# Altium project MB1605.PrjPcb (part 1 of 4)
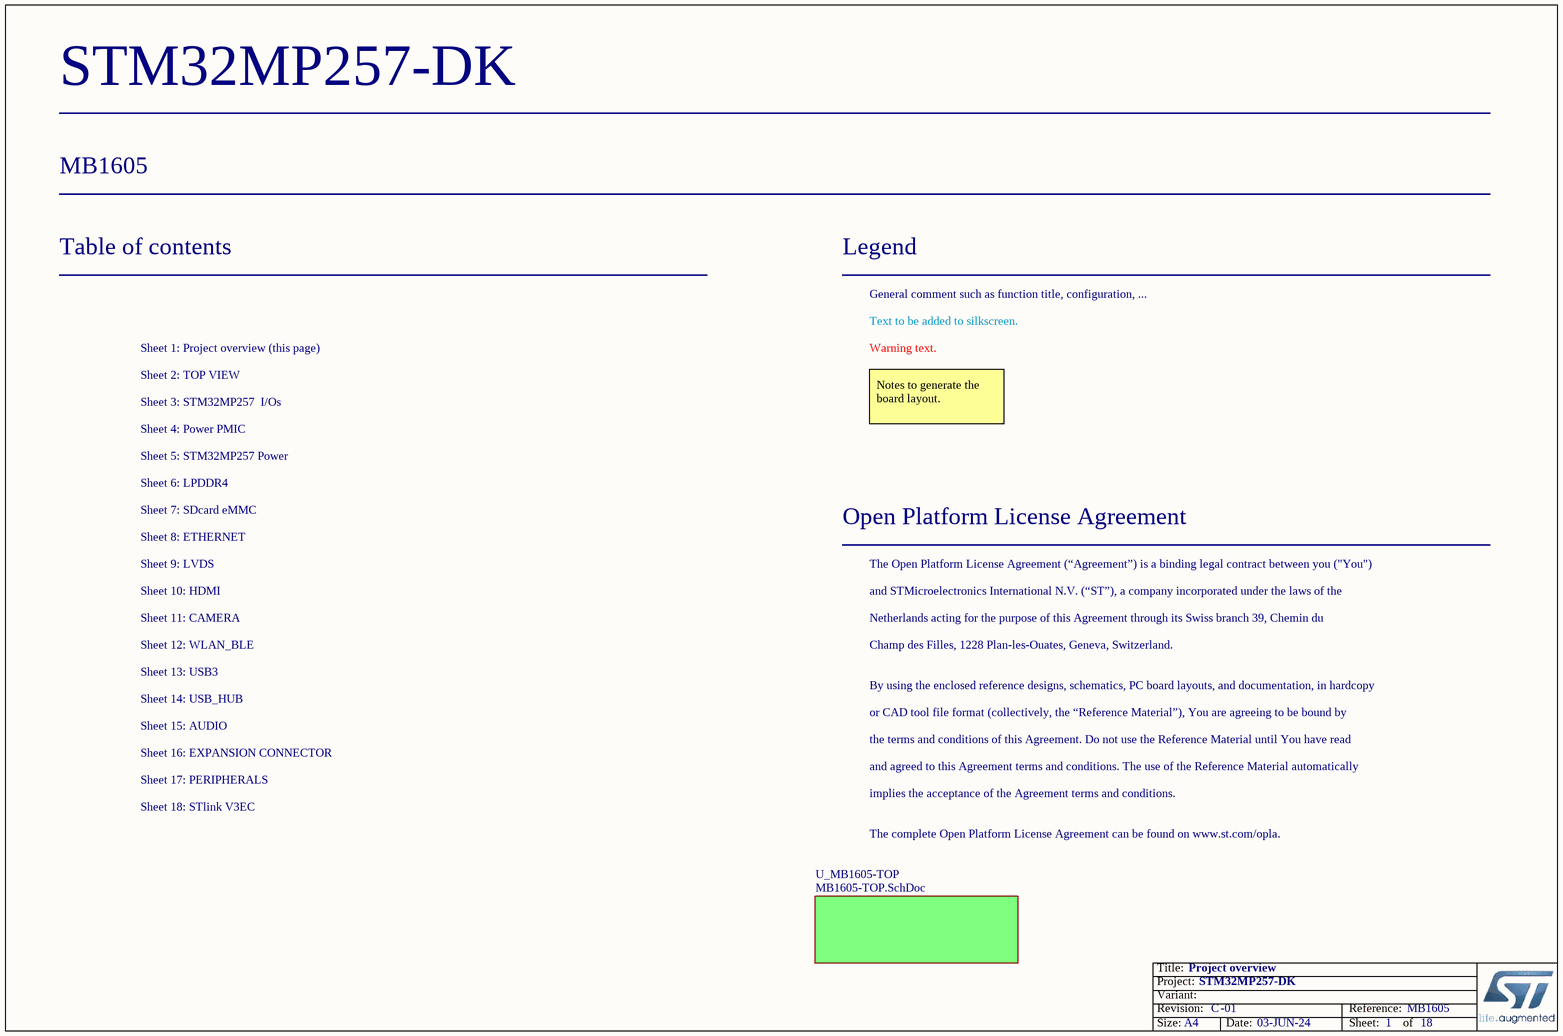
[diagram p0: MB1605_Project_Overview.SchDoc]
Board_Reference: MB1605; Board_PCB_Revision: C; Board_Name: STM32MP257-DK; Board_Document_Date: 03-JUN-24; Board_Assembly_Revision: 01
18 sheets, 641 parts. Net scope: flat (ports and power ports of the same name join across sheets).
Board file: MB1605.PcbDoc
Sheets:
  MB1605_Project_Overview.SchDoc
    U_MB1605-TOP = MB1605-TOP.SchDoc
      U_WLAN_BLUETOOTH = WLAN_BLUETOOTH.SchDoc
      U_Peripherals = Peripherals.SchDoc
      U_MP257_14x14 = MP257_14x14.SchDoc
      U_Power_PMIC = Power_PMIC.SchDoc
      U_Power_MPU = Power_MPU.SchDoc
      U_LVDS = LVDS.SchDoc
      U_STLINK_V3EC = STLINK_V3EC.SchDoc
      U_USB_HUB = USB_HUB.SchDoc
      U_USB3 = USB3.SchDoc
      U_CAMERA = CAMERA.SchDoc
      U_AUDIO = AUDIO.SchDoc
      U_Expansion_Connector = Expansion_Connector.SchDoc
      U_LPDDR4 = LPDDR4.SchDoc
      U_SDcard_eMMC = SDcard_eMMC.SchDoc
      U_ETHERNET = ETHERNET.SchDoc
      U_HDMI = HDMI.SchDoc

## Sheet MB1605_Project_Overview.SchDoc: Project overview
size A4; Date: Not used; ApprovedBy: Not used; CheckedBy: Not used; Author: Not used; CompanyName: STMicroelectronics; DrawnBy: Not used; Engineer: Not used; Organization: Not used; Address1: Not used; Address2: Not used; Address3: Not used; Address4: Not used; DocumentNumber: Not used; Revision: Not used; SheetNumber: 1; SheetTotal: 18

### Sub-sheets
U_MB1605-TOP = MB1605-TOP.SchDoc: no entries

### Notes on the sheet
- Table of contents
- Legend
- General comment such as function title, configuration, ...
- Sheet 1: Project overview (this page)
- Sheet 2: TOP VIEW
- Text to be added to silkscreen.
- Warning text.
- Sheet 3: STM32MP257  I/Os
- Sheet 4: Power PMIC
- Notes to generate the board layout.
- Sheet 5: STM32MP257 Power
- Sheet 7: SDcard eMMC
- Sheet 6: LPDDR4
- Sheet 8: ETHERNET
- Sheet 9: LVDS
- Open Platform License Agreement
- The Open Platform License Agreement (“Agreement”) is a binding legal contract between you ("You")
- Sheet 10: HDMI
- Sheet 11: CAMERA
- Sheet 12: WLAN_BLE
- and STMicroelectronics International N.V. (“ST”), a company incorporated under the laws of the
- Netherlands acting for the purpose of this Agreement through its Swiss branch 39, Chemin du
- Champ des Filles, 1228 Plan-les-Ouates, Geneva, Switzerland.
- Sheet 13: USB3
- Sheet 14: USB_HUB
- By using the enclosed reference designs, schematics, PC board layouts, and documentation, in hardcopy
- or CAD tool file format (collectively, the “Reference Material”), You are agreeing to be bound by
- Sheet 17: PERIPHERALS
- Sheet 16: EXPANSION CONNECTOR
- Sheet 15: AUDIO
- the terms and conditions of this Agreement. Do not use the Reference Material until You have read
- and agreed to this Agreement terms and conditions. The use of the Reference Material automatically
- Sheet 18: STlink V3EC
- implies the acceptance of the Agreement terms and conditions.
- The complete Open Platform License Agreement can be found on www.st.com/opla.

## Sheet MB1605-TOP.SchDoc: MB1605-TOP
size A3; Date: Not used; ApprovedBy: Not used; CheckedBy: Not used; Author: Not used; CompanyName: STMicroelectronics; DrawnBy: Not used; Engineer: Not used; Organization: Not used; Address1: Not used; Address2: Not used; Address3: Not used; Address4: Not used; DocumentNumber: Not used; Revision: Not used; SheetNumber: 2; SheetTotal: 18
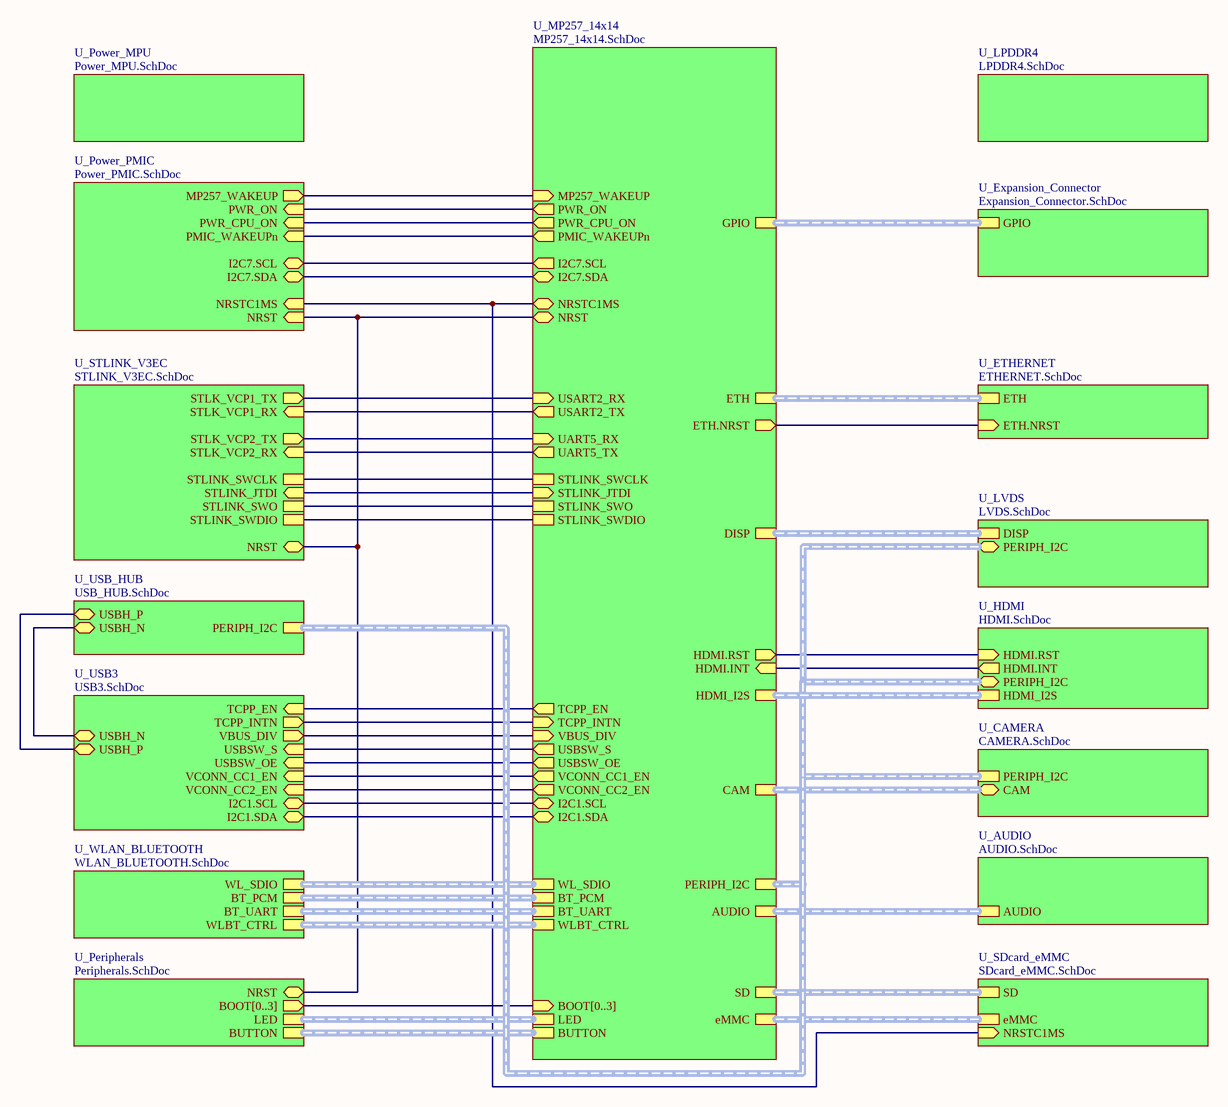
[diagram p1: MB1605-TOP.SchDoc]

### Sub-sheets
U_AUDIO = AUDIO.SchDoc: AUDIO (harness AUDIO)
U_CAMERA = CAMERA.SchDoc: CAM (bidir, harness CAMERA), PERIPH_I2C (harness PERIPH_I2C)
U_ETHERNET = ETHERNET.SchDoc: ETH.NRST (in), ETH (harness ETH1)
U_Expansion_Connector = Expansion_Connector.SchDoc: GPIO (harness GPIO)
U_HDMI = HDMI.SchDoc: HDMI.RST (in), HDMI.INT (out), PERIPH_I2C (bidir, harness PERIPH_I2C), HDMI_I2S (harness HDMI_I2S)
U_LPDDR4 = LPDDR4.SchDoc: no entries
U_LVDS = LVDS.SchDoc: DISP (harness DISP), PERIPH_I2C (bidir, harness PERIPH_I2C)
U_MP257_14x14 = MP257_14x14.SchDoc: NRST (bidir), PWR_ON (out), ETH (harness ETH1), BOOT[0..3] (in), LED (harness LED), BUTTON (harness BUTTON), UART5_TX (out), UART5_RX (in), STLINK_SWCLK, STLINK_JTDI (in), STLINK_SWO, STLINK_SWDIO, USART2_RX (in), NRSTC1MS (bidir), VBUS_DIV (in), TCPP_INTN (in), GPIO (harness GPIO), I2C7.SDA (bidir), I2C7.SCL (out), USART2_TX (out), DISP (harness DISP), PERIPH_I2C (harness PERIPH_I2C), ETH.NRST (out), I2C1.SCL (bidir), HDMI_I2S (harness HDMI_I2S), I2C1.SDA (bidir), PWR_CPU_ON (out), CAM (harness CAMERA), SD (harness SD), WL_SDIO (harness WL_SDIO), BT_PCM (harness BT_PCM), WLBT_CTRL (harness WL_BT_CTRL), BT_UART (harness BT_UART), AUDIO (harness AUDIO), MP257_WAKEUP (in), PMIC_WAKEUPn (out), HDMI.INT (in), HDMI.RST (out), USBSW_OE (out), USBSW_S (out), eMMC (harness eMMC), TCPP_EN (out), VCONN_CC1_EN (out), VCONN_CC2_EN (out)
U_Peripherals = Peripherals.SchDoc: NRST (bidir), BOOT[0..3] (out), LED (harness LED), BUTTON (harness BUTTON)
U_Power_MPU = Power_MPU.SchDoc: no entries
U_Power_PMIC = Power_PMIC.SchDoc: PMIC_WAKEUPn (in), NRST (in), I2C7.SCL (bidir), PWR_ON (in), PWR_CPU_ON (in), NRSTC1MS (in), I2C7.SDA (bidir), MP257_WAKEUP (out)
U_SDcard_eMMC = SDcard_eMMC.SchDoc: SD (harness SD), eMMC (harness eMMC), NRSTC1MS (in)
U_STLINK_V3EC = STLINK_V3EC.SchDoc: NRST (bidir), STLK_VCP2_TX (out), STLK_VCP2_RX (in), STLK_VCP1_TX (out), STLK_VCP1_RX (in), STLINK_SWO, STLINK_SWDIO, STLINK_SWCLK, STLINK_JTDI (in)
U_USB3 = USB3.SchDoc: TCPP_INTN (out), I2C1.SDA (bidir), I2C1.SCL (bidir), VBUS_DIV (out), USBH_P (bidir), USBH_N (bidir), USBSW_OE (in), USBSW_S (in), TCPP_EN (in), VCONN_CC1_EN (in), VCONN_CC2_EN (in)
U_USB_HUB = USB_HUB.SchDoc: USBH_P (bidir), USBH_N (bidir), PERIPH_I2C (harness PERIPH_I2C)
U_WLAN_BLUETOOTH = WLAN_BLUETOOTH.SchDoc: BT_PCM (harness BT_PCM), BT_UART (harness BT_UART), WL_SDIO (harness WL_SDIO), WLBT_CTRL (harness WL_BT_CTRL)

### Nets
(unnamed): sheet U_Peripherals/NRST, sheet U_MP257_14x14/NRST, sheet U_Power_PMIC/NRST, sheet U_STLINK_V3EC/NRST
(unnamed): sheet U_MP257_14x14/PWR_ON, sheet U_Power_PMIC/PWR_ON  [a separate net that carries the same name]
(unnamed): sheet U_MP257_14x14/UART5_TX, sheet U_STLINK_V3EC/STLK_VCP2_RX  [a separate net that carries the same name]
(unnamed): sheet U_MP257_14x14/UART5_RX, sheet U_STLINK_V3EC/STLK_VCP2_TX  [a separate net that carries the same name]
(unnamed): sheet U_MP257_14x14/STLINK_SWCLK, sheet U_STLINK_V3EC/STLINK_SWCLK  [a separate net that carries the same name]
(unnamed): sheet U_MP257_14x14/STLINK_JTDI, sheet U_STLINK_V3EC/STLINK_JTDI  [a separate net that carries the same name]
(unnamed): sheet U_MP257_14x14/STLINK_SWO, sheet U_STLINK_V3EC/STLINK_SWO  [a separate net that carries the same name]
(unnamed): sheet U_MP257_14x14/STLINK_SWDIO, sheet U_STLINK_V3EC/STLINK_SWDIO  [a separate net that carries the same name]
(unnamed): sheet U_MP257_14x14/USART2_RX, sheet U_STLINK_V3EC/STLK_VCP1_TX  [a separate net that carries the same name]
(unnamed): sheet U_MP257_14x14/NRSTC1MS, sheet U_Power_PMIC/NRSTC1MS, sheet U_SDcard_eMMC/NRSTC1MS  [a separate net that carries the same name]
(unnamed): sheet U_MP257_14x14/VBUS_DIV, sheet U_USB3/VBUS_DIV  [a separate net that carries the same name]
(unnamed): sheet U_MP257_14x14/TCPP_INTN, sheet U_USB3/TCPP_INTN  [a separate net that carries the same name]
(unnamed): sheet U_MP257_14x14/I2C7.SDA, sheet U_Power_PMIC/I2C7.SDA  [a separate net that carries the same name]
(unnamed): sheet U_MP257_14x14/I2C7.SCL, sheet U_Power_PMIC/I2C7.SCL  [a separate net that carries the same name]
(unnamed): sheet U_MP257_14x14/USART2_TX, sheet U_STLINK_V3EC/STLK_VCP1_RX  [a separate net that carries the same name]
(unnamed): sheet U_MP257_14x14/ETH.NRST, sheet U_ETHERNET/ETH.NRST  [a separate net that carries the same name]
(unnamed): sheet U_MP257_14x14/I2C1.SCL, sheet U_USB3/I2C1.SCL  [a separate net that carries the same name]
(unnamed): sheet U_MP257_14x14/I2C1.SDA, sheet U_USB3/I2C1.SDA  [a separate net that carries the same name]
(unnamed): sheet U_MP257_14x14/PWR_CPU_ON, sheet U_Power_PMIC/PWR_CPU_ON  [a separate net that carries the same name]
(unnamed): sheet U_MP257_14x14/MP257_WAKEUP, sheet U_Power_PMIC/MP257_WAKEUP  [a separate net that carries the same name]
(unnamed): sheet U_MP257_14x14/PMIC_WAKEUPn, sheet U_Power_PMIC/PMIC_WAKEUPn  [a separate net that carries the same name]
(unnamed): sheet U_MP257_14x14/HDMI.INT, sheet U_HDMI/HDMI.INT  [a separate net that carries the same name]
(unnamed): sheet U_MP257_14x14/HDMI.RST, sheet U_HDMI/HDMI.RST  [a separate net that carries the same name]
(unnamed): sheet U_MP257_14x14/USBSW_OE, sheet U_USB3/USBSW_OE  [a separate net that carries the same name]
(unnamed): sheet U_MP257_14x14/USBSW_S, sheet U_USB3/USBSW_S  [a separate net that carries the same name]
(unnamed): sheet U_MP257_14x14/TCPP_EN, sheet U_USB3/TCPP_EN  [a separate net that carries the same name]
(unnamed): sheet U_MP257_14x14/VCONN_CC1_EN, sheet U_USB3/VCONN_CC1_EN  [a separate net that carries the same name]
(unnamed): sheet U_MP257_14x14/VCONN_CC2_EN, sheet U_USB3/VCONN_CC2_EN  [a separate net that carries the same name]
(unnamed): sheet U_USB_HUB/USBH_P, sheet U_USB3/USBH_P  [a separate net that carries the same name]
(unnamed): sheet U_USB_HUB/USBH_N, sheet U_USB3/USBH_N  [a separate net that carries the same name]

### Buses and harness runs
bus sheet U_MP257_14x14/BOOT[0..3] = sheet U_Peripherals/BOOT[0..3]
harness sheet U_AUDIO/AUDIO = sheet U_MP257_14x14/AUDIO
harness sheet U_CAMERA/CAM = sheet U_MP257_14x14/CAM
harness sheet U_CAMERA/PERIPH_I2C = sheet U_HDMI/PERIPH_I2C = sheet U_LVDS/PERIPH_I2C = sheet U_MP257_14x14/PERIPH_I2C = sheet U_USB_HUB/PERIPH_I2C
harness sheet U_ETHERNET/ETH = sheet U_MP257_14x14/ETH
harness sheet U_Expansion_Connector/GPIO = sheet U_MP257_14x14/GPIO
harness sheet U_HDMI/HDMI_I2S = sheet U_MP257_14x14/HDMI_I2S
harness sheet U_LVDS/DISP = sheet U_MP257_14x14/DISP
harness sheet U_MP257_14x14/BT_PCM = sheet U_WLAN_BLUETOOTH/BT_PCM
harness sheet U_MP257_14x14/BT_UART = sheet U_WLAN_BLUETOOTH/BT_UART
harness sheet U_MP257_14x14/BUTTON = sheet U_Peripherals/BUTTON
harness sheet U_MP257_14x14/eMMC = sheet U_SDcard_eMMC/eMMC
harness sheet U_MP257_14x14/LED = sheet U_Peripherals/LED
harness sheet U_MP257_14x14/SD = sheet U_SDcard_eMMC/SD
harness sheet U_MP257_14x14/WL_SDIO = sheet U_WLAN_BLUETOOTH/WL_SDIO
harness sheet U_MP257_14x14/WLBT_CTRL = sheet U_WLAN_BLUETOOTH/WLBT_CTRL

## Sheet WLAN_BLUETOOTH.SchDoc: WLAN_BLUETOOTH
size A4; Date: 21-MAR-2018; Author: A.B; CompanyName: STMicroelectronics; Organization: MCD/TOOLS/GNB; Address1: 12, Rue Jules HOROWITZ; Address2: 38019 Grenoble; Address3: FRANCE; DocumentNumber: MB1605; Revision: B-01; SheetNumber: 12; SheetTotal: 18; Project: STM32MP257
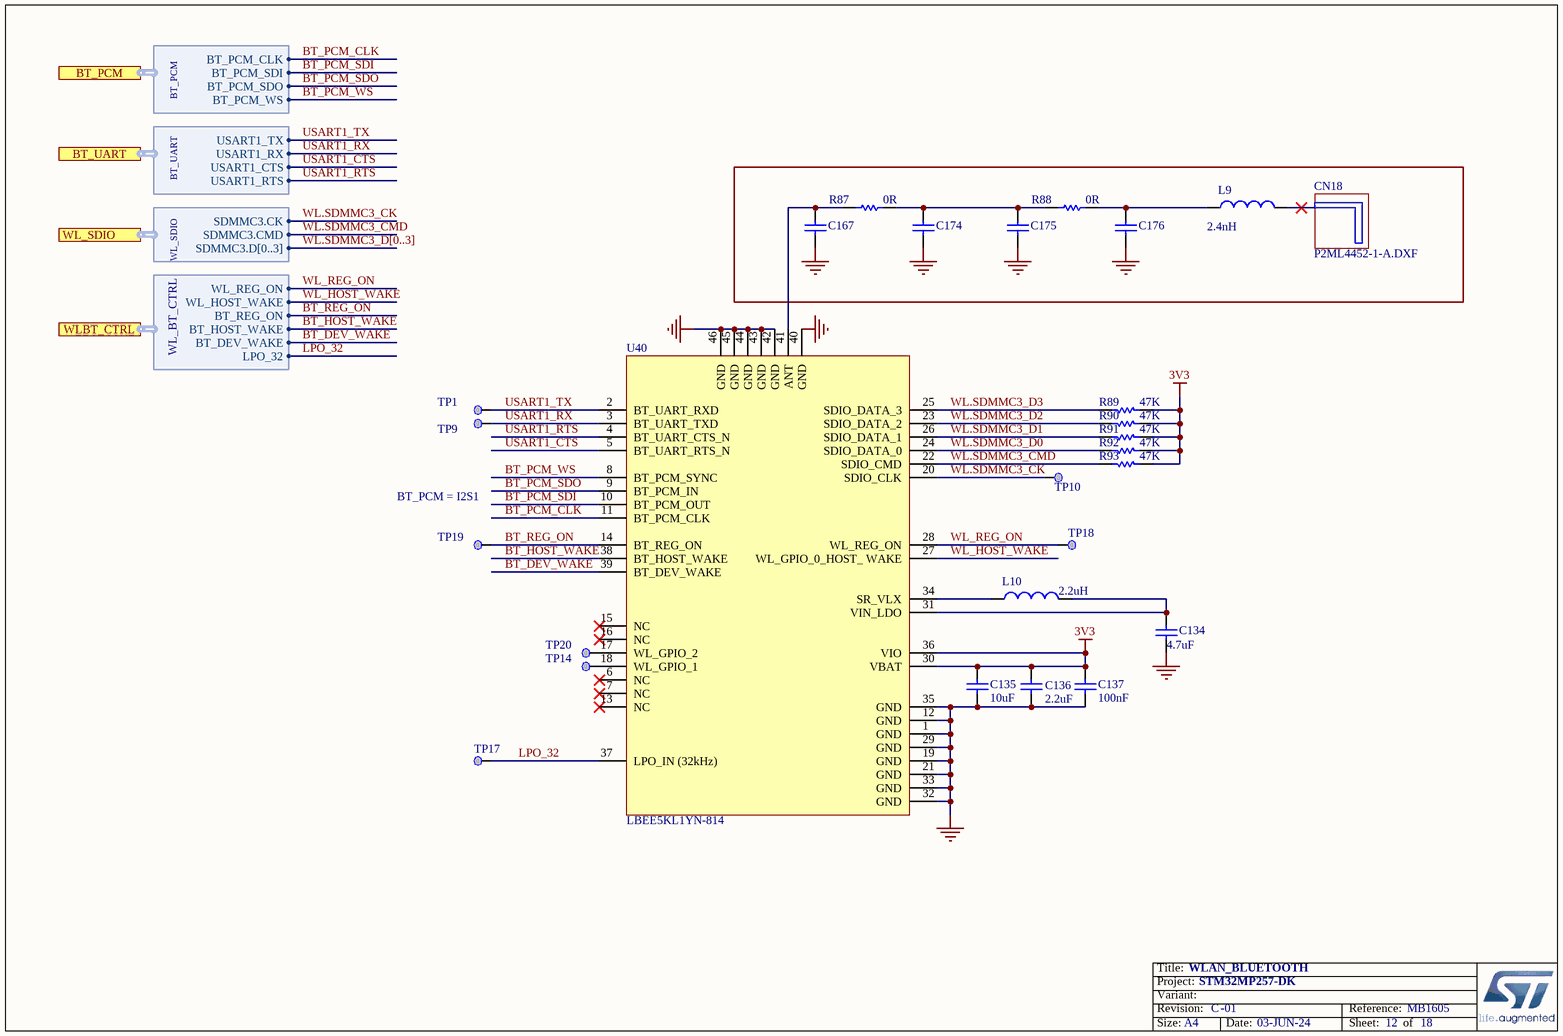
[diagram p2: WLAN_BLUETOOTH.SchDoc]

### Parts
C134  value 4.7uF  [C0402]  (hidden comment: Capacitor)
C135  value 10uF  [C0603]  (hidden comment: Capacitor)
C136  value 2.2uF  [C0603]  (hidden comment: Capacitor)
C137  value 100nF  [C0402]
C167  Capacitor  [C0402]  (value not drawn)
C174  Capacitor  [C0402]  (value not drawn)
C175  Capacitor  [C0402]  (value not drawn)
C176  Capacitor  [C0402]  (value not drawn)
CN18  value P2ML4452-1-A.DXF  [ANT_MURATA_TYPE-1-DX_P2ML4452-1-A_DXF]  (hidden comment: antenna_Wifi_BLE_Murata)  (no BOM)
L9  value 2.4nH  [IND_0402_MURATA_LQW15AN2N4C00X]  (hidden comment: Inductor)
L10  value 2.2uH  [L0603]  (hidden comment: Inductor)
R87  value 0R  [R0402]  (hidden comment: Resistor)
R88  value 0R  [R0402]  (hidden comment: Resistor)
R89  value 47K  [R0402]  (hidden comment: Resistor)
R90  value 47K  [R0402]  (hidden comment: Resistor)
R91  value 47K  [R0402]  (hidden comment: Resistor)
R92  value 47K  [R0402]  (hidden comment: Resistor)
R93  value 47K  [R0402]  (hidden comment: Resistor)
TP1  Test Point  [TP_SMD_0-6MM]  (value not drawn)  (no BOM)
TP9  Test Point  [TP_SMD_0-6MM]  (value not drawn)  (no BOM)
TP10  Test Point  [TP_SMD_0-6MM]  (value not drawn)  (no BOM)
TP14  Test Point  [TP_SMD_0-6MM]  (value not drawn)  (no BOM)
TP17  Test Point  [TP_SMD_0-6MM]  (value not drawn)  (no BOM)
TP18  Test Point  [TP_SMD_0-6MM]  (value not drawn)  (no BOM)
TP19  Test Point  [TP_SMD_0-6MM]  (value not drawn)  (no BOM)
TP20  Test Point  [TP_SMD_0-6MM]  (value not drawn)  (no BOM)
U40  LBEE5KL1YN-814  [MOD_WLAN-BT_MURATA_LBEE5KL1YN-814]

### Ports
BT_PCM (harness BT_PCM), BT_UART (harness BT_UART), WL_SDIO (harness WL_SDIO), WLBT_CTRL (harness WL_BT_CTRL)

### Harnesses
BT_PCM: BT_PCM_CLK, BT_PCM_SDI, BT_PCM_SDO, BT_PCM_WS
BT_UART: USART1_TX, USART1_RX, USART1_CTS, USART1_RTS
WL_SDIO: SDMMC3.CMD, SDMMC3.CK, SDMMC3.D[0..3]
WL_BT_CTRL: WL_REG_ON, WL_HOST_WAKE, BT_REG_ON, BT_HOST_WAKE, BT_DEV_WAKE, LPO_32

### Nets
3V3: C135.2 C136.2 C137.2 R89.1 R90.1 R91.1 R92.1 R93.1 U40.30(VBAT) U40.36(VIO)
GND: C134.1 C135.1 C136.1 C137.1 C167.1 C174.1 C175.1 C176.1 U40.1(GND) U40.12(GND) U40.19(GND) U40.21(GND) U40.29(GND) U40.32(GND) U40.33(GND) U40.35(GND) U40.40(GND) U40.42(GND) U40.43(GND) U40.44(GND) U40.45(GND) U40.46(GND)
BT_DEV_WAKE: U40.39(BT_DEV_WAKE) ; port WLBT_CTRL.BT_DEV_WAKE
BT_HOST_WAKE: U40.38(BT_HOST_WAKE) ; port WLBT_CTRL.BT_HOST_WAKE
BT_PCM_CLK: U40.11(BT_PCM_CLK) ; port BT_PCM.BT_PCM_CLK
BT_PCM_SDI: U40.10(BT_PCM_OUT) ; port BT_PCM.BT_PCM_SDI
BT_PCM_SDO: U40.9(BT_PCM_IN) ; port BT_PCM.BT_PCM_SDO
BT_PCM_WS: U40.8(BT_PCM_SYNC) ; port BT_PCM.BT_PCM_WS
BT_REG_ON: TP19.1 U40.14(BT_REG_ON) ; port WLBT_CTRL.BT_REG_ON
LPO_32: TP17.1 U40.37(LPO_IN_(32kHz)) ; port WLBT_CTRL.LPO_32
USART1_CTS: U40.5(BT_UART_RTS_N) ; port BT_UART.USART1_CTS
USART1_RTS: U40.4(BT_UART_CTS_N) ; port BT_UART.USART1_RTS
USART1_RX: TP9.1 U40.3(BT_UART_TXD) ; port BT_UART.USART1_RX
USART1_TX: TP1.1 U40.2(BT_UART_RXD) ; port BT_UART.USART1_TX
WL.SDMMC3_CK: TP10.1 U40.20(SDIO_CLK) ; port WL_SDIO.SDMMC3.CK
WL.SDMMC3_CMD: R93.2 U40.22(SDIO_CMD) ; port WL_SDIO.SDMMC3.CMD
WL.SDMMC3_D0: R92.2 U40.24(SDIO_DATA_0)
WL.SDMMC3_D1: R91.2 U40.26(SDIO_DATA_1)
WL.SDMMC3_D2: R90.2 U40.23(SDIO_DATA_2)
WL.SDMMC3_D3: R89.2 U40.25(SDIO_DATA_3)
WL_HOST_WAKE: U40.27(WL_GPIO_0_HOST__WAKE) ; port WLBT_CTRL.WL_HOST_WAKE
WL_REG_ON: TP18.1 U40.28(WL_REG_ON) ; port WLBT_CTRL.WL_REG_ON
NetC134_2: C134.2 L10.2 U40.31(VIN_LDO)
NetC167_2: C167.2 R87.2 U40.41(ANT)
NetC174_2: C174.2 C175.2 R87.1 R88.2
NetC176_2: C176.2 L9.1 R88.1
NetL10_1: L10.1 U40.34(SR_VLX)
NetTP14_1: TP14.1 U40.18(WL_GPIO_1)
NetTP20_1: TP20.1 U40.17(WL_GPIO_2)

Not connected (* = marked no-connect by the designer): L9 2*; U40 6(NC)* 7(NC)* 13(NC)* 15(NC)* 16(NC)*

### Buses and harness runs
bus WL.SDMMC3_D[0..3]

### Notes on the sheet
- (near TP19) BT_PCM = I2S1

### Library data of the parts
C134 = MCD-01356: Capacitor, MLCC, 4.7uF, 6V3, X5R, 20%, 0402, T=0,5mm; Manufacturer_Part_Number: GRM155R60J475ME47; Manufacturer: MURATA; Alternate_Manufacturer_Part_Number: GRM155R60J475ME87; Part_Preference: Recommended; Provided_By: SUBCO; Order_Code_RS: 814-5230; ECCN_EU: NEC; ECCN_US: EAR99; Component_Country_Of_Origin: Japan; ID: 3456; ShowFields: YES
C135 = MCD-00099: Capacitor, MLCC, 10uF, 10V, X5R, 10%, 0603, T=0,8mm; Manufacturer_Part_Number: GRM188R61A106KE69D; Manufacturer: MURATA; Part_Preference: Recommended; ECCN_US: EAR99; ECCN_EU: NEC; Provided_By: SUBCO; Initial_Board_Reference: MB1262; Order_Code_RS: 170-6168; Component_Country_Of_Origin: Japan; ID: 2770; ShowFields: YES
C136 = MCD-00012: Capacitor, MLCC, 2.2uF, 10V, X5R, 10%, 0603, T=0,8mm; Manufacturer_Part_Number: CC0603KRX5R6BB225; Manufacturer: YAGEO; Alternate_Manufacturer_Part_Number: C0603C225K8PACTU; Alternate_Manufacturer: KEMET; BMS_Part_Number: 9142010; Part_Preference: Recommended; ECCN_US: EAR99; ECCN_EU: NEC; Provided_By: SUBCO; Initial_Board_Reference: MB1274; Component_Country_Of_Origin: China; ID: 2467; ShowFields: YES
C137 = MCD-00006: Capacitor,100nF,16V,X7R,10%,0402; Manufacturer_Part_Number: CC0402KRX7R7BB104; Manufacturer: YAGEO; Alternate_Manufacturer: MURATA; Alternate_Manufacturer_Part_Number: GCM155R71C104KA55D; Part_Preference: Recommended; Partial_Alternate_Internal_Part_Number: MCD-03299; ECCN_US: EAR99; ECCN_EU: NEC; Provided_By: SUBCO; Initial_Board_Reference: MB1274; Order_Code_RS: 616-9701; Component_Country_Of_Origin: China; ID: 2474; ShowFields: YES; Alternate_EMS: M
C167 C174-C176 = MCD-00200: Capacitor, MLCC, 12pF, 50V, NPO, 5%, 0402, T=0,5mm; Manufacturer_Part_Number: CC0402JRNPO9BN120; Manufacturer: YAGEO; Part_Preference: Recommended; Provided_By: SUBCO; ECCN_EU: NEC; ECCN_US: EAR99; Component_Country_Of_Origin: China; ID: 2667; ShowFields: YES
CN18 = MCD-00656: Murata_Type1DX_AntennaDesign_P2ML4452-1-A.DXF; Part_Type: Misc; Manufacturer: MURATA; Part_Preference: Recommended; Initial_Board_Reference: MB1272; Component_Country_Of_Origin: Unknown; ID: 3086; ShowFields: YES
L9 = MCD-00657: Inductor,2.4nH,+-0.2nH,0.05R,0.85A,0402; Manufacturer_Part_Number: LQW15AN2N4C00#; Manufacturer: MURATA; Part_Preference: Recommended; Provided_By: SUBCO; Initial_Board_Reference: MB1272; Order_Code_RS: 177-6240; Component_Country_Of_Origin: Japan; ID: 3088; ShowFields: YES
L10 = MCD-00659: Inductor, 2.2µH, 20%, Isat 0.35A, DCR 0.2Ohm, 0603; Manufacturer_Part_Number: LQM18PN2R2MGH; Manufacturer: MURATA; Part_Preference: Recommended; Provided_By: SUBCO; Initial_Board_Reference: MB1272; Component_Country_Of_Origin: Japan; ID: 3085; ShowFields: YES
R87 R88 = MCD-00052: Resistor,0R,0402,5%,1/16W; Manufacturer_Part_Number: RC0402JR-070RL; Manufacturer: YAGEO; Part_Preference: Recommended; ECCN_US: EAR99; ECCN_EU: NEC; Provided_By: SUBCO; Initial_Board_Reference: MB1274; Order_Code_RS: 618-5804; Component_Country_Of_Origin: China; ID: 2540; ShowFields: YES
R89-R93 = MCD-00063: Resistor,47K,0402,1%,1/16W; Manufacturer_Part_Number: RC0402FR-0747KL; Manufacturer: YAGEO; Part_Preference: Recommended; ECCN_US: EAR99; ECCN_EU: NEC; Provided_By: SUBCO; Initial_Board_Reference: MB1274; Component_Country_Of_Origin: China; ID: 2528; ShowFields: YES
TP1 TP9 TP10 TP14 TP17-TP20 = MCD-00631: Test Point 0.6mm; Part_Type: Misc; Part_Preference: Recommended; Initial_Board_Reference: MB1264; ID: 3108; ShowFields: YES
U40 = MCD-03465: IC, IEEE802.11b/g/n W-LAN + Bluetooth 5.2(BR/EDR/BLE) module; Part_Preference: Recommended; Manufacturer: MURATA; Component_Country_Of_Origin: China°; ShowFields: YES; ID: 5581

## Sheet Peripherals.SchDoc: Peripherals
size A4; Date: 01-DEC-2013; CompanyName: STMicroelectronics; Organization: Microcontrollers Division; Address1: 12, Rue Jules HOROWITZ; Address2: 38019 Grenoble; Address3: FRANCE; DocumentNumber: MB1272; Revision: A-01; SheetNumber: 17; SheetTotal: 18; Project: STM32MP15-DISCO PI
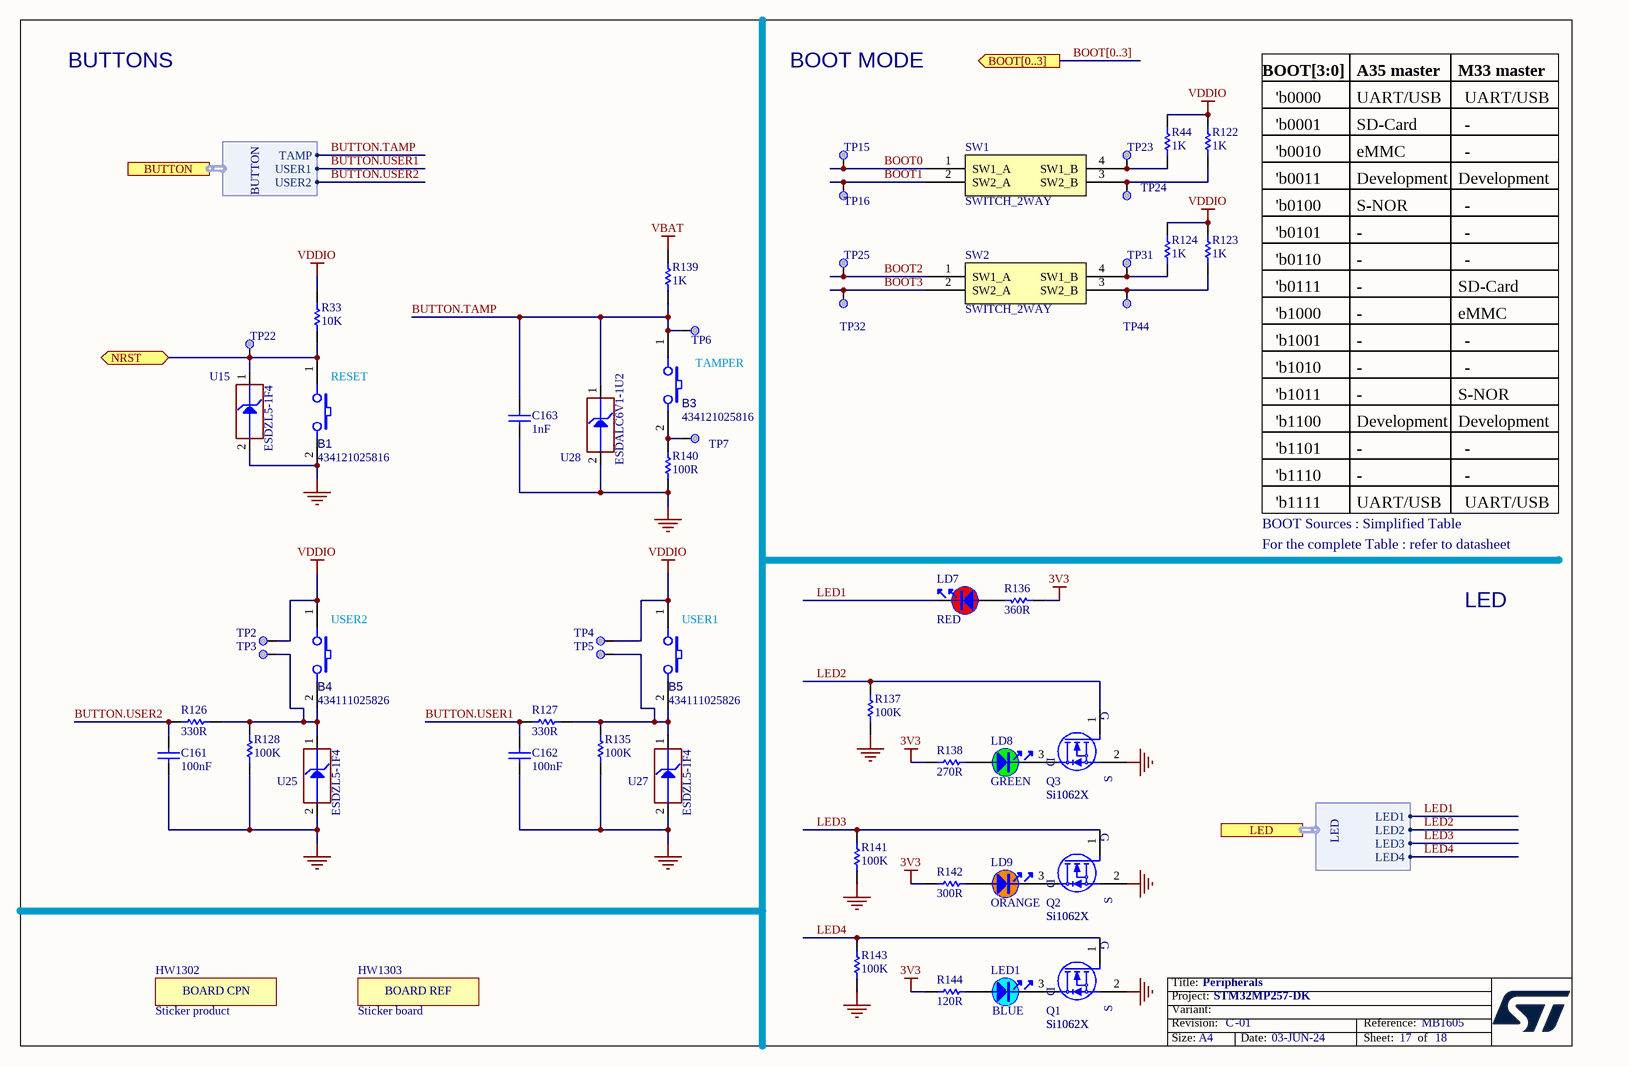
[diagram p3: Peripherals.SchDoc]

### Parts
B1  value 434121025816  [SWI_WE_434121025816]  (hidden comment: SW_PUSH_SMD_2P)
B3  value 434121025816  [SWI_WE_434121025816]  (hidden comment: SW_PUSH_SMD_2P)
B4  value 434111025826  [SWI_WE_4341x10258x6]  (hidden comment: SW_PUSH_SMD_2P)
B5  value 434111025826  [SWI_WE_4341x10258x6]  (hidden comment: SW_PUSH_SMD_2P)
C161  value 100nF  [C0402]  (hidden comment: Capacitor)
C162  value 100nF  [C0402]  (hidden comment: Capacitor)
C163  value 1nF  [C0402]  (hidden comment: Capacitor)
HW1302  value Sticker product  [STICKER_BOARD-CPN_25X5]  (hidden comment: ​PCH W35 footprint requested to have a space on board for stickers.)  (mechanical)
HW1303  value Sticker board  [STICKER_BOARD-REF_25X5]  (hidden comment: STICKER_BOARD_REF)  (mechanical)
LD7  value RED  [LED_0603_VISHAY_VLMS1300-GS08_RED_1A2K_H0P8]  (hidden comment: LED_red)
LD8  value GREEN  [LED_0603_OSRAM_LG-Q396-PS-35_GREEN_1A2K_H0P4]  (hidden comment: LED_green)
LD9  value ORANGE  [LED_0603_OSRAM_LO-Q976-PS-25_ORANGE_1A2K_H0P8]  (hidden comment: LED_orange)
LED1  value BLUE  [LED_0603_OSRAM_LB-Q39G-L2OO-35-1_BLUE_1A2K_H0P4]
Q1  value Si1062X  Manufacturer_Part_Number: Si1062X  [MOS_SC89-3L]  (hidden comment: MOSFET_N-CHANNEL)
Q2  value Si1062X  Manufacturer_Part_Number: Si1062X  [MOS_SC89-3L]  (hidden comment: MOSFET_N-CHANNEL)
Q3  value Si1062X  Manufacturer_Part_Number: Si1062X  [MOS_SC89-3L]  (hidden comment: MOSFET_N-CHANNEL)
R33  value 10K  [R0402]  (hidden comment: Resistor)
R44  value 1K  [R0402]  (hidden comment: Resistor)
R122  value 1K  [R0402]  (hidden comment: Resistor)
R123  value 1K  [R0402]  (hidden comment: Resistor)
R124  value 1K  [R0402]  (hidden comment: Resistor)
R126  value 330R  [R0402]  (hidden comment: Resistor)
R127  value 330R  [R0402]  (hidden comment: Resistor)
R128  value 100K  [R0402]  (hidden comment: Resistor)
R135  value 100K  [R0402]  (hidden comment: Resistor)
R136  value 360R  [R0402]  (hidden comment: Resistor)
R137  value 100K  [R0402]  (hidden comment: Resistor)
R138  value 270R  [R0402]  (hidden comment: Resistor)
R139  value 1K  [R0402]  (hidden comment: Resistor)
R140  value 100R  [R0402]  (hidden comment: Resistor)
R141  value 100K  [R0402]  (hidden comment: Resistor)
R142  value 300R  [R0402]  (hidden comment: Resistor)
R143  value 100K  [R0402]  (hidden comment: Resistor)
R144  value 120R  [R0402]
SW1  SWITCH_2WAY  [SWI_C&K_SDA02H1SBD_2POS]
SW2  SWITCH_2WAY  [SWI_C&K_SDA02H1SBD_2POS]
TP2  Test Point  [TP_SMD_1MM]  (value not drawn)  (no BOM)
TP3  Test Point  [TP_SMD_1MM]  (value not drawn)  (no BOM)
TP4  Test Point  [TP_SMD_1MM]  (value not drawn)  (no BOM)
TP5  Test Point  [TP_SMD_1MM]  (value not drawn)  (no BOM)
TP6  Test Point  [TP_SMD_1MM]  (value not drawn)  (no BOM)
TP7  Test Point  [TP_SMD_1MM]  (value not drawn)  (no BOM)
TP15  Test Point  [TP_SMD_1MM]  (value not drawn)  (no BOM)
TP16  Test Point  [TP_SMD_1MM]  (value not drawn)  (no BOM)
TP22  Test Point  [TP_SMD_1MM]  (value not drawn)  (no BOM)
TP23  Test Point  [TP_SMD_1MM]  (value not drawn)  (no BOM)
TP24  Test Point  [TP_SMD_1MM]  (value not drawn)  (no BOM)
TP25  Test Point  [TP_SMD_1MM]  (value not drawn)  (no BOM)
TP31  Test Point  [TP_SMD_1MM]  (value not drawn)  (no BOM)
TP32  Test Point  [TP_SMD_1MM]  (value not drawn)  (no BOM)
TP44  Test Point  [TP_SMD_1MM]  (value not drawn)  (no BOM)
U15  value ESDZL5-1F4  [ESD_ST0201]  (hidden comment: ESD-TRANSIL)
U25  value ESDZL5-1F4  [ESD_ST0201]  (hidden comment: ESD-TRANSIL)
U27  value ESDZL5-1F4  [ESD_ST0201]  (hidden comment: ESD-TRANSIL)
U28  value ESDALC6V1-1U2  [ESD_ST0201]  (hidden comment: ESD-TRANSIL)

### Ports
BOOT[0..3] (out), BUTTON (harness BUTTON), LED (harness LED), NRST (bidir)

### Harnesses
BUTTON: TAMP, USER1, USER2
LED: LED1, LED2, LED3, LED4

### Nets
3V3: R136.1 R138.2 R142.2 R144.1
GND: B1.2 C161.1 C162.1 C163.1 Q1.2(S) Q2.2(S) Q3.2(S) R128.1 R135.1 R137.1 R140.2 R141.1 R143.1 U15.2(GND) U25.2(GND) U27.2(GND) U28.2(GND)
VBAT: R139.2
VDDIO: B4.1 B5.1 R33.2 R44.2 R122.2 R123.2 R124.2 TP2.1 TP4.1
BOOT0: SW1.1(SW1_A) TP15.1
BOOT1: SW1.2(SW2_A) TP16.1
BOOT2: SW2.1(SW1_A) TP25.1
BOOT3: SW2.2(SW2_A) TP32.1
BUTTON.TAMP: B3.1 C163.2 R139.1 TP6.1 U28.1(IO1) ; port BUTTON.TAMP
BUTTON.USER1: C162.2 R127.1 ; port BUTTON.USER1
BUTTON.USER2: C161.2 R126.1 ; port BUTTON.USER2
LED1: LD7.2 ; port LED.LED1
LED2: Q3.1(G) R137.2 ; port LED.LED2
LED3: Q2.1(G) R141.2 ; port LED.LED3
LED4: Q1.1(G) R143.2 ; port LED.LED4
NRST: B1.1 R33.1 TP22.1 U15.1(IO1) ; port NRST
NetB3_2: B3.2 R140.1 TP7.1
NetB4_2: B4.2 R126.2 R128.2 TP3.1 U25.1(IO1)
NetB5_2: B5.2 R127.2 R135.2 TP5.1 U27.1(IO1)
NetLD7_1: LD7.1 R136.2
NetLD8_1: LD8.1 R138.1
NetLD8_2: LD8.2 Q3.3(D)
NetLD9_1: LD9.1 R142.1
NetLD9_2: LD9.2 Q2.3(D)
NetLED1_1: LED1.1 R144.2
NetLED1_2: LED1.2 Q1.3(D)
NetR44_1: R44.1 SW1.4(SW1_B) TP23.1
NetR122_1: R122.1 SW1.3(SW2_B) TP24.1
NetR123_1: R123.1 SW2.3(SW2_B) TP44.1
NetR124_1: R124.1 SW2.4(SW1_B) TP31.1

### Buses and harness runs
bus BOOT[0..3] = port BOOT[0..3]

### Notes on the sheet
- BUTTONS
- BOOT MODE
- BOOT[3:0]
- 'b0001
- 'b0000
- A35 master
- UART/USB
- SD-Card
- M33 master
- -
- 'b0010
- 'b0011
- eMMC
- Development
- 'b0100
- 'b0101
- 'b0110
- S-NOR
- 'b0111
- 'b1000
- (near B1) RESET
- TAMPER
- 'b1001
- 'b1010
- 'b1011
- 'b1100
- 'b1101
- BOOT Sources : Simplified Table
- 'b1110
- 'b1111
- For the complete Table : refer to datasheet
- (near B4) USER2
- (near B5) USER1
- LED

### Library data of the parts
B1 B3 = MCD-03492: Switch tactile, SPST-NO, 50mA, 12V, 6x3.8mm; Part_Type: Misc; Part_Preference: Recommended; Manufacturer: WURTH ELEKTRONIC; ShowFields: YES; ID: 5608; Component_Country_Of_Origin: China°
B4 B5 = MCD-03491: Switch tactile, SPST-NO, 50mA, 12V, 6x3.8mm; Part_Type: Misc; Part_Preference: Recommended; Manufacturer: WURTH ELEKTRONIC; ShowFields: YES; ID: 5607; Component_Country_Of_Origin: China°
C161 C162 = MCD-00006: Capacitor, MLCC, 100nF, 16V, X7R, +/-10%, 0402, T=0.5mm; Manufacturer_Part_Number: CC0402KRX7R7BB104; Manufacturer: YAGEO; Part_Preference: Recommended; Alternate_Manufacturer: MURATA; Alternate_Manufacturer_Part_Number: GCM155R71C104KA55D; Partial_Alternate_Internal_Part_Number: MCD-03299; Order_Code_RS: 616-9701; Component_Country_Of_Origin: China; ID: 2474; ShowFields: YES; Alternate_EMS: M
C163 = MCD-00198: Capacitor, MLCC, 1nF, 16V, X7R, +/-10%, 0402, T=0.5mm; Part_Preference: Recommended; Manufacturer: YAGEO; Manufacturer_Part_Number: CC0402KRX7R7BB102; Component_Country_Of_Origin: China; ShowFields: YES; ID: 2665
HW1302 = MCD-00547: Sticker to mention board CPN code; Part_Type: Misc; Part_Preference: Recommended; Provided_By: SUBCO; Initial_Board_Reference: MB1319; ID: 3197; ShowFields: YES
HW1303 = MCD-00235: Sticker to mention board reference + serial number; Part_Type: Misc; Part_Preference: Recommended; Provided_By: SUBCO; Initial_Board_Reference: MB1319; ID: 2632; ShowFields: YES
LD7 = MCD-00587: LED Red, 0603 SMD, 2V Forward Voltage; Part_Type: Display; Manufacturer_Part_Number: VLMS1300-GS08; Manufacturer: VISHAY; Alternate_Manufacturer_Part_Number: LS Q976-NR-1; Alternate_Manufacturer: OSRAM OPTO SEMICONDUCTORS; Alternate_Internal_Part_Number: MCD-02401; Part_Preference: Recommended; Provided_By: SUBCO; Component_Country_Of_Origin: China; ID: 3154; ShowFields: YES
LD8 = MCD-00588: LED Green, 0603 SMD, Forward Voltage Typ=2V, Max=2.5V; Part_Type: Display; Manufacturer_Part_Number: LG Q396-PS-35; Manufacturer: OSRAM OPTO SEMICONDUCTORS; Alternate_Manufacturer_Part_Number: VLMTG1300-GS08; Alternate_Manufacturer: VISHAY SEMICONDUCTOR OPTO DIVISION; Alternate_Internal_Part_Number: MCD-02400; Part_Preference: Recommended; Provided_By: SUBCO; Component_Country_Of_Origin: Unknown; ID: 3155; ShowFields: YES
LD9 = MCD-00590: LED Orange, 0603 SMD, Forward Voltage Min=1.6V, Max=2.4V; Part_Type: Display; Manufacturer_Part_Number: LO Q976-PS-25; Manufacturer: OSRAM OPTO SEMICONDUCTORS; Alternate_Manufacturer_Part_Number: VLMO1300-GS08; Alternate_Manufacturer: VISHAY SEMICONDUCTOR OPTO DIVISION; Part_Preference: Recommended; Provided_By: SUBCO; Component_Country_Of_Origin: Unknown; ID: 3156; ShowFields: YES
LED1 = MCD-00585: LED Blue, 0603 SMD, Forward Voltage Min=2,8V, Max=3,8V; Part_Type: Display; Manufacturer_Part_Number: LB Q39G-L2OO-35-1; Manufacturer: OSRAM OPTO SEMICONDUCTORS; Alternate_Manufacturer_Part_Number: 19-217-BHC-ZL1M2RY-3T-V4; Alternate_Manufacturer: EVERLIGHT; Alternate_Internal_Part_Number: MCD-02398; Part_Preference: Recommended; Order_Code_RS: 9148643; Provided_By: SUBCO; Component_Country_Of_Origin: Unknown; ID: 3159; ShowFields: YES
Q1-Q3 = MCD-02221: MOSFET N-CH 20V SC-89; Part_Preference: Recommended; Part_Type: Transistor; Manufacturer: VISHAY; Order_Code_RS: 812-3044; Component_Country_Of_Origin: Philippines; ID: 4321; ShowFields: YES
R33 = MCD-00053: Resistor,10K,0402,1%,1/16W; Manufacturer_Part_Number: RC0402FR-0710KL; Manufacturer: YAGEO; BMS_Part_Number: 9131590; Part_Preference: Recommended; Component_Country_Of_Origin: China; ID: 2539; ShowFields: YES
R44 R122-R124 = MCD-00061: Resistor,1K,0402,1%,1/16W; Part_Preference: Recommended; Manufacturer: YAGEO; Manufacturer_Part_Number: RC0402FR-071KL; Component_Country_Of_Origin: China; ID: 2532; ShowFields: YES
R126 R127 = MCD-00062: Resistor,330R,0402,1%,1/16W; Manufacturer_Part_Number: RC0402FR-07330RL; Manufacturer: YAGEO; Part_Preference: Recommended; Component_Country_Of_Origin: China; ID: 2529; ShowFields: YES
R128 R135 R137 R141 R143 = MCD-00059: Resistor,100K,0402,1%,1/16W; Manufacturer_Part_Number: RC0402FR-07100KL; Manufacturer: YAGEO; Alternate_Manufacturer_Part_Number: RT0402FRE07100KL; Part_Preference: Recommended; Partial_Alternate_Internal_Part_Number: MCD-03301; Component_Country_Of_Origin: China; ID: 2533; ShowFields: YES; Alternate_EMS: M
R136 = MCD-00461: Resistor,360R,0402,1%,1/16W; Manufacturer_Part_Number: RC0402FR-07360RL; Manufacturer: YAGEO; Part_Preference: Recommended; Provided_By: SUBCO; ECCN_US: EAR99; ECCN_EU: NEC; Component_Country_Of_Origin: China; ID: 2816; ShowFields: YES
R138 = MCD-00441: Resistor,270R,0402,1%,1/16W; Manufacturer_Part_Number: RC0402FR-07270RL; Manufacturer: YAGEO; Part_Preference: Recommended; Provided_By: SUBCO; ECCN_US: EAR99; ECCN_EU: NEC; Component_Country_Of_Origin: China; ID: 2838; ShowFields: YES
R139 = MCD-00061: Resistor, 1K, 0402, +/-1%,1/16W; Manufacturer_Part_Number: RC0402FR-071KL; Manufacturer: YAGEO; Part_Preference: Recommended; Component_Country_Of_Origin: China; ShowFields: YES; ID: 2532
R140 = MCD-00067: Resistor, 100R, 0402, +/- 1%, 1/16W; Manufacturer_Part_Number: RC0402FR-07100RL; Manufacturer: YAGEO; Part_Preference: Recommended; Component_Country_Of_Origin: China; ShowFields: YES; ID: 2527
R142 = MCD-00449: Resistor,300R,0402,1%,1/16W; Manufacturer_Part_Number: RC0402FR-07300RL; Manufacturer: YAGEO; Part_Preference: Recommended; Provided_By: SUBCO; ECCN_US: EAR99; ECCN_EU: NEC; Component_Country_Of_Origin: China; ID: 2832; ShowFields: YES
R144 = MCD-00194: Resistor,120R,0402,1%,1/16W; Manufacturer_Part_Number: RC0402FR-07120RL; Manufacturer: YAGEO; Part_Preference: Recommended; Provided_By: SUBCO; ECCN_US: EAR99; ECCN_EU: NEC; Component_Country_Of_Origin: China; ID: 2674; ShowFields: YES
SW1 SW2 = MCD-00658: Dip Switch ,2Position ,Surface Mount Slide (Standard) ,2.54 pitch,25mA 24VDC; Part_Type: Misc; Part_Preference: Recommended; Manufacturer: C&K; Manufacturer_Part_Number: SDA02H1SBD; Component_Country_Of_Origin: Malaysia; ShowFields: YES; ID: 3090
TP2-TP7 TP15 TP16 TP22-TP25 TP31 TP32 TP44 = MCD-00074: Test Point 1mm; Part_Type: Misc; Part_Preference: Recommended; Initial_Board_Reference: MB1274; ID: 2518; ShowFields: YES
U15 U25 = MCD-03501: ESD protection , 0201; Part_Type: IC; Manufacturer: STMICROELECTRONICS; Part_Preference: Recommended; Order_Code_RS: 163-7318; ID: 5617; ShowFields: YES
U27 = MCD-03501: ESD protection , 0201; Part_Type: IC; Part_Preference: Recommended; Manufacturer: STMICROELECTRONICS; Order_Code_RS: 163-7318; ShowFields: YES; ID: 5617
U28 = MCD-00170: ESD protection 6V1; Part_Type: Diode; Manufacturer: STMICROELECTRONICS; BMS_Part_Number: 9151132; Part_Preference: Recommended; Manufacturer_HQ_COO: EU; Component_Country_Of_Origin: China; ID: 2696; ShowFields: YES

## Sheet MP257_14x14.SchDoc: STM32MP257  I/Os
size A3; Date: Not used; ApprovedBy: Not used; CheckedBy: Not used; Author: Not used; CompanyName: STMicroelectronics; DrawnBy: Not used; Engineer: Not used; Organization: Not used; Address1: Not used; Address2: Not used; Address3: Not used; Address4: Not used; DocumentNumber: Not used; Revision: Not used; SheetNumber: 3; SheetTotal: 18
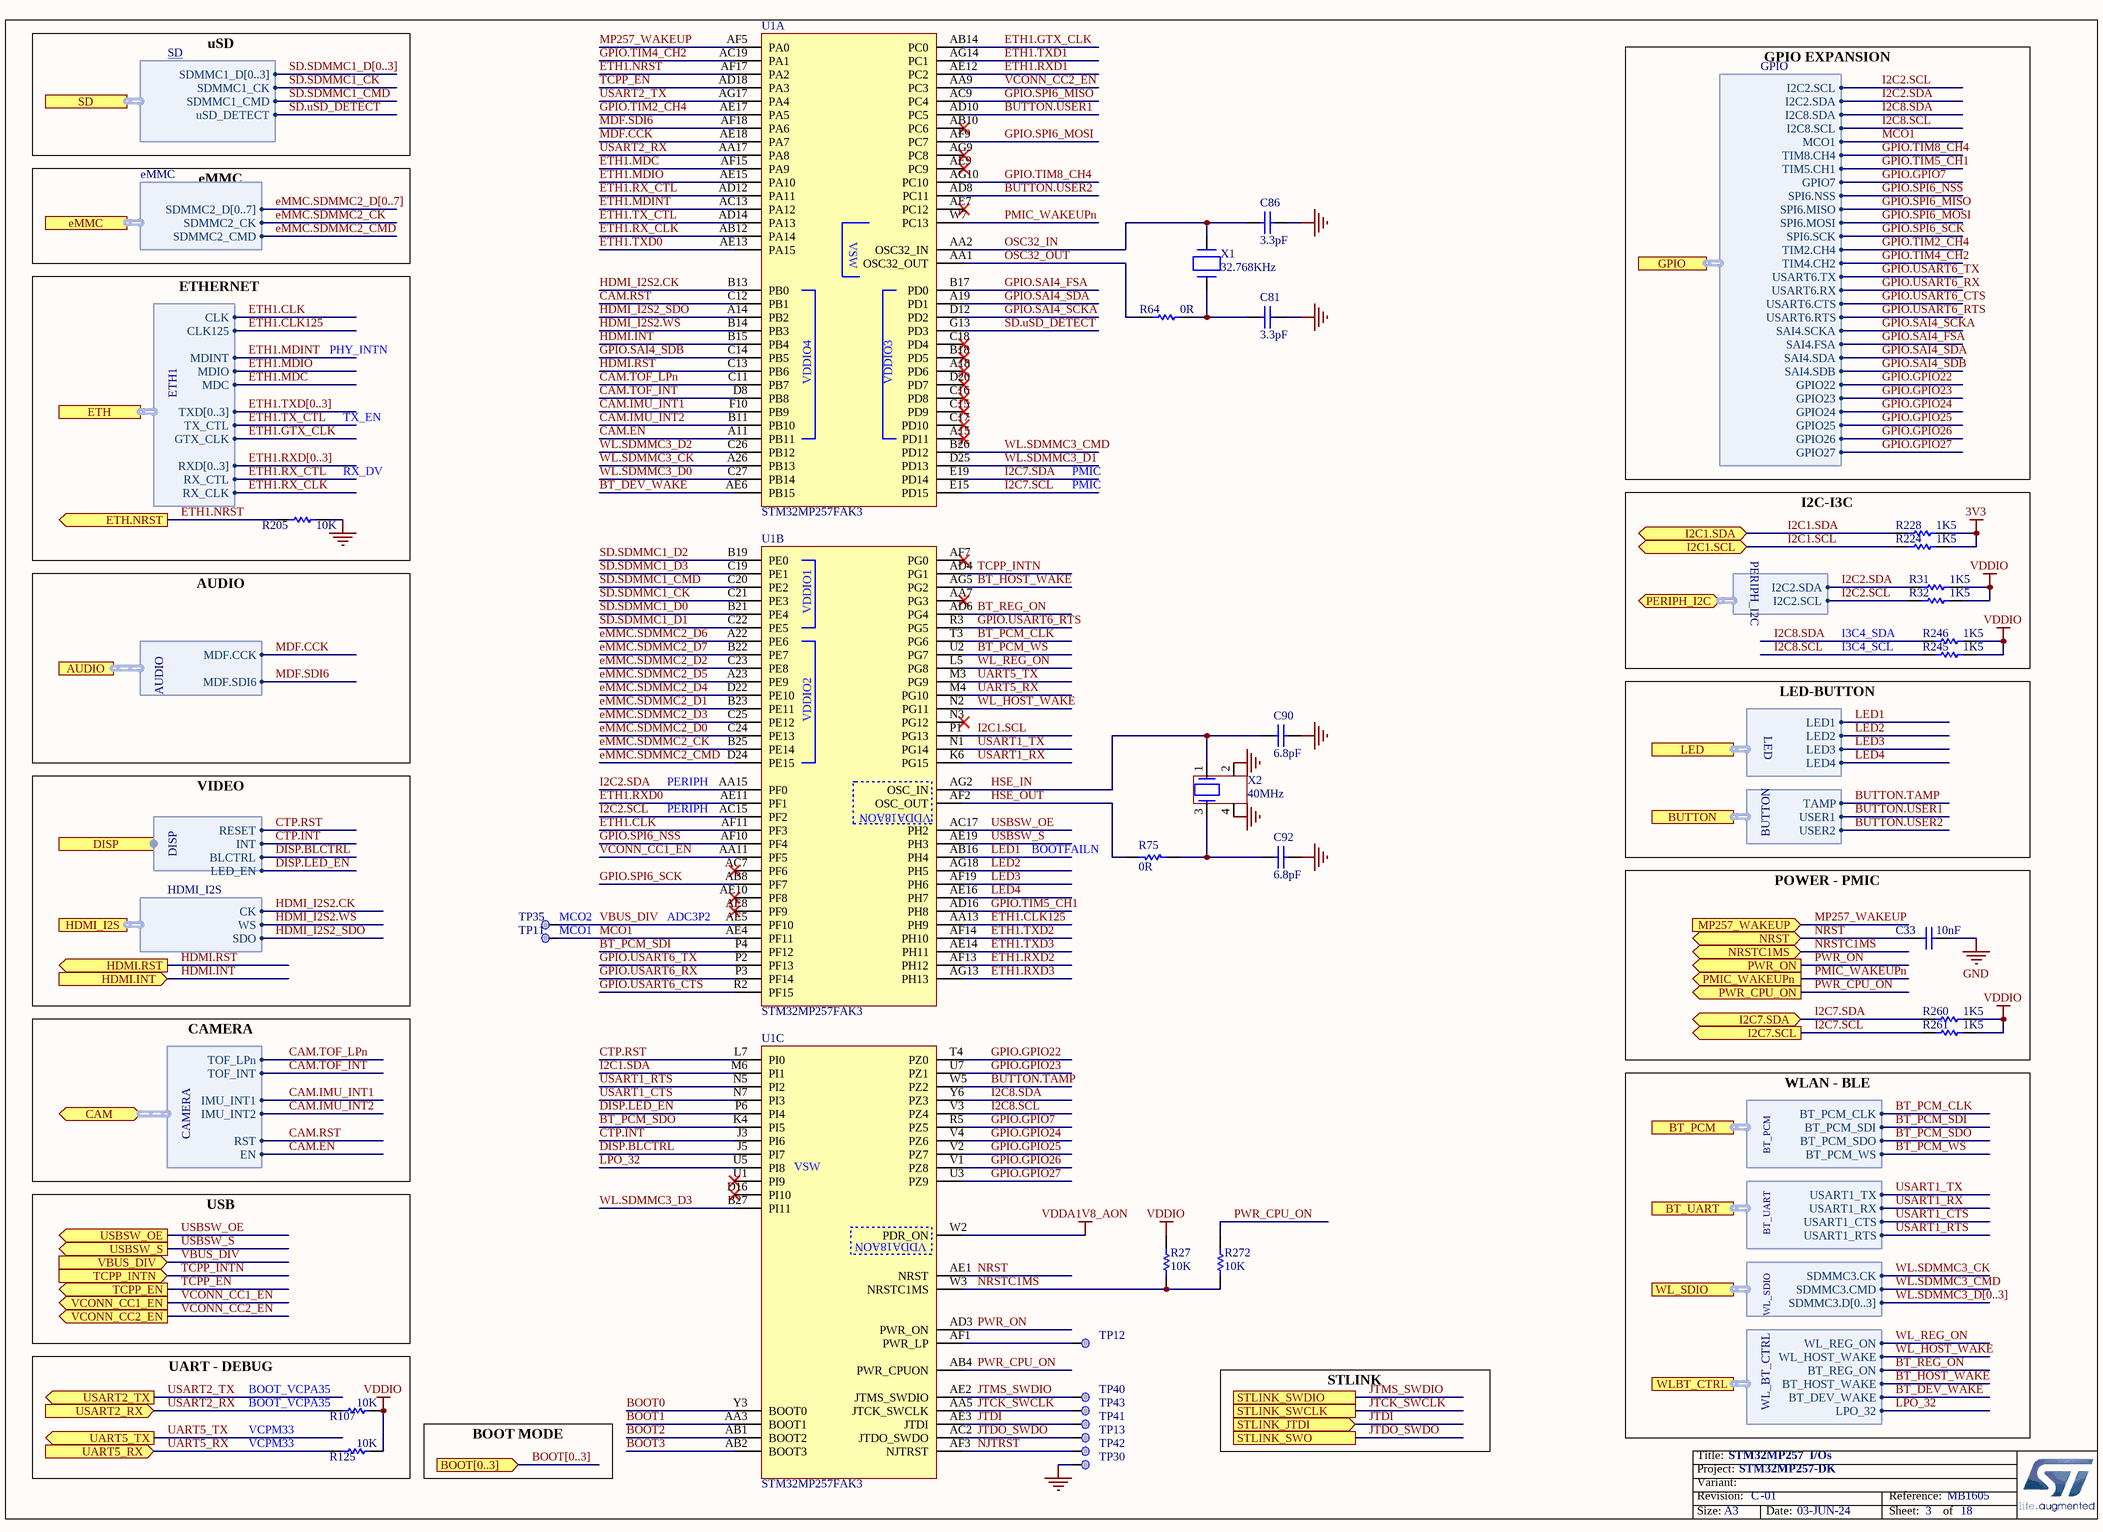
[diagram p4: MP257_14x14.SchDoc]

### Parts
C33  value 10nF  [C0402]  (hidden comment: Capacitor)
C81  value 3.3pF  [C0402]  (hidden comment: Capacitor)
C86  value 3.3pF  [C0402]  (hidden comment: Capacitor)
C90  value 6.8pF  [C0402]  (hidden comment: Capacitor)
C92  value 6.8pF  [C0402]  (hidden comment: Capacitor)
R27  value 10K  [R0402]  (hidden comment: Resistor)
R31  value 1K5  [R0402]  (hidden comment: Resistor)
R32  value 1K5  [R0402]  (hidden comment: Resistor)
R64  value 0R  [R0402]
R75  value 0R  [R0402]
R107  value 10K  [R0402]  (hidden comment: Resistor)
R125  value 10K  [R0402]  (hidden comment: Resistor)
R205  value 10K  [R0402]  (hidden comment: Resistor)
R224  value 1K5  [R0402]  (hidden comment: Resistor)
R228  value 1K5  [R0402]  (hidden comment: Resistor)
R245  value 1K5  [R0402]  (hidden comment: Resistor)
R246  value 1K5  [R0402]  (hidden comment: Resistor)
R260  value 1K5  [R0402]  (hidden comment: Resistor)
R261  value 1K5  [R0402]  (hidden comment: Resistor)
R272  value 10K  [R0402]  (hidden comment: Resistor)
TP11  Test Point  [TP_SMD_1MM]  (value not drawn)  (no BOM)
TP12  Test Point  [TP_SMD_1MM]  (value not drawn)  (no BOM)
TP13  Test Point  [TP_SMD_1MM]  (value not drawn)  (no BOM)
TP30  Test Point  [TP_SMD_1MM]  (value not drawn)  (no BOM)
TP35  Test Point  [TP_SMD_1MM]  (value not drawn)  (no BOM)
TP40  Test Point  [TP_SMD_1MM]  (value not drawn)  (no BOM)
TP41  Test Point  [TP_SMD_1MM]  (value not drawn)  (no BOM)
TP42  Test Point  [TP_SMD_1MM]  (value not drawn)  (no BOM)
TP43  Test Point  [TP_SMD_1MM]  (value not drawn)  (no BOM)
U1  STM32MP257FAK3  [ICC_TFBGA424_14X14_P050_H1P20_CODE-B0A2]  (parts A,B,C of 9)
X1  value 32.768KHz  [CRY_NX2012SA_2P]  (hidden comment: XTAL_2_PINS)
X2  value 40MHz  [CRY_NX1612SA_4P]  (hidden comment: XTAL_4_PINS)

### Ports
AUDIO (harness AUDIO), BOOT[0..3] (in), BT_PCM (harness BT_PCM), BT_UART (harness BT_UART), BUTTON (harness BUTTON), CAM (bidir, harness CAMERA), DISP (harness DISP), eMMC (harness eMMC), ETH (harness ETH1), ETH.NRST (out), GPIO (harness GPIO), HDMI.INT (in), HDMI.RST (out), HDMI_I2S (harness HDMI_I2S), I2C1.SCL (bidir), I2C1.SDA (bidir), I2C7.SCL (out), I2C7.SDA (bidir), LED (harness LED), MP257_WAKEUP (in), NRST (bidir), NRSTC1MS (bidir), PERIPH_I2C (bidir, harness PERIPH_I2C), PMIC_WAKEUPn (out), PWR_CPU_ON (out), PWR_ON (out), SD (harness SD), STLINK_JTDI (in), STLINK_SWCLK, STLINK_SWDIO, STLINK_SWO, TCPP_EN (out), TCPP_INTN (in), UART5_RX (in), UART5_TX (out), USART2_RX (in), USART2_TX (out), USBSW_OE (out), USBSW_S (out), VBUS_DIV (in), VCONN_CC1_EN (out), VCONN_CC2_EN (out), WL_SDIO (harness WL_SDIO), WLBT_CTRL (harness WL_BT_CTRL)

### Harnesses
ETH1: MDINT, CLK125, TXD[0..3], MDIO, MDC, RX_CLK, GTX_CLK, TX_CTL, RXD[0..3], RX_CTL, CLK
HDMI_I2S: CK, SDO, WS
GPIO: I2C2.SCL, I2C2.SDA, I2C8.SDA, MCO1, TIM8.CH4, TIM5.CH1, GPIO7, SPI6.NSS, SPI6.MISO, SPI6.MOSI, SPI6.SCK, TIM2.CH4, TIM4.CH2, USART6.TX, USART6.RX, USART6.CTS, USART6.RTS, I2C8.SCL, SAI4.SCKA, SAI4.FSA, SAI4.SDA, SAI4.SDB, GPIO22, GPIO23, GPIO24, GPIO25, GPIO26, GPIO27
PERIPH_I2C: I2C2.SDA, I2C2.SCL
LED: LED1, LED2, LED3, LED4
BUTTON: TAMP, USER1, USER2
CAMERA: TOF_LPn, TOF_INT, IMU_INT1, IMU_INT2, RST, EN
DISP: RESET, INT, BLCTRL, LED_EN
SD: SDMMC1_D[0..3], SDMMC1_CK, SDMMC1_CMD, uSD_DETECT
BT_PCM: BT_PCM_CLK, BT_PCM_SDI, BT_PCM_SDO, BT_PCM_WS
BT_UART: USART1_TX, USART1_RX, USART1_CTS, USART1_RTS
WL_SDIO: SDMMC3.CMD, SDMMC3.CK, SDMMC3.D[0..3]
WL_BT_CTRL: WL_REG_ON, WL_HOST_WAKE, BT_REG_ON, BT_HOST_WAKE, BT_DEV_WAKE, LPO_32
eMMC: SDMMC2_CK, SDMMC2_CMD, SDMMC2_D[0..7]
AUDIO: MDF.CCK, MDF.SDI6

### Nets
3V3: R224.2 R228.2
GND: C33.1 C81.2 C86.2 C90.1 C92.2 R205.2 TP30.1 X2.2 X2.4
VDDA1V8_AON: U1.W2(PDR_ON)
VDDIO: R27.2 R31.2 R32.2 R107.2 R125.2 R245.2 R246.2 R260.2 R261.2
BOOT0: U1.Y3(BOOT0)
BOOT1: U1.AA3(BOOT1)
BOOT2: U1.AB1(BOOT2)
BOOT3: U1.AB2(BOOT3)
BT_DEV_WAKE: U1.AE6(PB15) ; port WLBT_CTRL.BT_DEV_WAKE
BT_HOST_WAKE: U1.AG5(PG2) ; port WLBT_CTRL.BT_HOST_WAKE
BT_PCM_CLK: U1.T3(PG6) ; port BT_PCM.BT_PCM_CLK
BT_PCM_SDI: U1.P4(PF12) ; port BT_PCM.BT_PCM_SDI
BT_PCM_SDO: U1.K4(PI5) ; port BT_PCM.BT_PCM_SDO
BT_PCM_WS: U1.U2(PG7) ; port BT_PCM.BT_PCM_WS
BT_REG_ON: U1.AD6(PG4) ; port WLBT_CTRL.BT_REG_ON
BUTTON.TAMP: U1.W5(PZ2) ; port BUTTON.TAMP
BUTTON.USER1: U1.AD10(PC5) ; port BUTTON.USER1
BUTTON.USER2: U1.AD8(PC11) ; port BUTTON.USER2
CAM.EN: U1.A11(PB11) ; port CAM.EN
CAM.IMU_INT1: U1.F10(PB9) ; port CAM.IMU_INT1
CAM.IMU_INT2: U1.B11(PB10) ; port CAM.IMU_INT2
CAM.RST: U1.C12(PB1) ; port CAM.RST
CAM.TOF_INT: U1.D8(PB8) ; port CAM.TOF_INT
CAM.TOF_LPn: U1.C11(PB7) ; port CAM.TOF_LPn
CTP.INT: U1.J3(PI6) ; port DISP.INT
CTP.RST: U1.L7(PI0) ; port DISP.RESET
DISP.BLCTRL: U1.J5(PI7) ; port DISP.BLCTRL
DISP.LED_EN: U1.P6(PI4) ; port DISP.LED_EN
eMMC.SDMMC2_CK: U1.B25(PE14) ; port eMMC.SDMMC2_CK
eMMC.SDMMC2_CMD: U1.D24(PE15) ; port eMMC.SDMMC2_CMD
eMMC.SDMMC2_D0: U1.C24(PE13)
eMMC.SDMMC2_D1: U1.B23(PE11)
eMMC.SDMMC2_D2: U1.C23(PE8)
eMMC.SDMMC2_D3: U1.C25(PE12)
eMMC.SDMMC2_D4: U1.D22(PE10)
eMMC.SDMMC2_D5: U1.A23(PE9)
eMMC.SDMMC2_D6: U1.A22(PE6)
eMMC.SDMMC2_D7: U1.B22(PE7)
ETH1.CLK: U1.AF11(PF3) ; port ETH.CLK
ETH1.CLK125: U1.AA13(PH9) ; port ETH.CLK125
ETH1.GTX_CLK: U1.AB14(PC0) ; port ETH.GTX_CLK
ETH1.MDC: U1.AF15(PA9) ; port ETH.MDC
ETH1.MDINT: U1.AC13(PA12) ; port ETH.MDINT
ETH1.MDIO: U1.AE15(PA10) ; port ETH.MDIO
ETH1.NRST: R205.1 U1.AF17(PA2) ; port ETH.NRST
ETH1.RX_CLK: U1.AB12(PA14) ; port ETH.RX_CLK
ETH1.RX_CTL: U1.AD12(PA11) ; port ETH.RX_CTL
ETH1.RXD0: U1.AE11(PF1)
ETH1.RXD1: U1.AE12(PC2)
ETH1.RXD2: U1.AF13(PH12)
ETH1.RXD3: U1.AG13(PH13)
ETH1.TX_CTL: U1.AD14(PA13) ; port ETH.TX_CTL
ETH1.TXD0: U1.AE13(PA15)
ETH1.TXD1: U1.AG14(PC1)
ETH1.TXD2: U1.AF14(PH10)
ETH1.TXD3: U1.AE14(PH11)
GPIO.GPIO7: U1.R5(PZ5) ; port GPIO.GPIO7  [project net EXP_GPIO7]
GPIO.GPIO22: U1.T4(PZ0) ; port GPIO.GPIO22  [project net EXP_GPIO22]
GPIO.GPIO23: U1.U7(PZ1) ; port GPIO.GPIO23  [project net EXP_GPIO23]
GPIO.GPIO24: U1.V4(PZ6) ; port GPIO.GPIO24  [project net EXP_GPIO24]
GPIO.GPIO25: U1.V2(PZ7) ; port GPIO.GPIO25  [project net EXP_GPIO25]
GPIO.GPIO26: U1.V1(PZ8) ; port GPIO.GPIO26  [project net EXP_GPIO26]
GPIO.GPIO27: U1.U3(PZ9) ; port GPIO.GPIO27  [project net EXP_GPIO27]
GPIO.SAI4_FSA: U1.B17(PD0) ; port GPIO.SAI4.FSA  [project net EXP_GPIO19]
GPIO.SAI4_SCKA: U1.D12(PD2) ; port GPIO.SAI4.SCKA  [project net EXP_GPIO18]
GPIO.SAI4_SDA: U1.A19(PD1) ; port GPIO.SAI4.SDA  [project net EXP_GPIO20]
GPIO.SAI4_SDB: U1.C14(PB5) ; port GPIO.SAI4.SDB  [project net EXP_GPIO21]
GPIO.SPI6_MISO: U1.AC9(PC4) ; port GPIO.SPI6.MISO  [project net EXP_GPIO9]
GPIO.SPI6_MOSI: U1.AF9(PC7) ; port GPIO.SPI6.MOSI  [project net EXP_GPIO10]
GPIO.SPI6_NSS: U1.AF10(PF4) ; port GPIO.SPI6.NSS  [project net EXP_GPIO8]
GPIO.SPI6_SCK: U1.AB8(PF7) ; port GPIO.SPI6.SCK  [project net EXP_GPIO11]
GPIO.TIM2_CH4: U1.AE17(PA5) ; port GPIO.TIM2.CH4  [project net EXP_GPIO12]
GPIO.TIM4_CH2: U1.AC19(PA1) ; port GPIO.TIM4.CH2  [project net EXP_GPIO13]
GPIO.TIM5_CH1: U1.AD16(PH8) ; port GPIO.TIM5.CH1  [project net EXP_GPIO6]
GPIO.TIM8_CH4: U1.AG10(PC10) ; port GPIO.TIM8.CH4  [project net EXP_GPIO5]
GPIO.USART6_CTS: U1.R2(PF15) ; port GPIO.USART6.CTS  [project net EXP_GPIO16]
GPIO.USART6_RTS: U1.R3(PG5) ; port GPIO.USART6.RTS  [project net EXP_GPIO17]
GPIO.USART6_RX: U1.P3(PF14) ; port GPIO.USART6.RX  [project net EXP_GPIO15]
GPIO.USART6_TX: U1.P2(PF13) ; port GPIO.USART6.TX  [project net EXP_GPIO14]
HDMI.INT: U1.B15(PB4) ; port HDMI.INT
HDMI.RST: U1.C13(PB6) ; port HDMI.RST
HDMI_I2S2.CK: U1.B13(PB0) ; port HDMI_I2S.CK
HDMI_I2S2.WS: U1.B14(PB3) ; port HDMI_I2S.WS
HDMI_I2S2_SDO: U1.A14(PB2) ; port HDMI_I2S.SDO
HSE_IN: C90.2 U1.AG2(OSC_IN) X2.1
HSE_OUT: R75.2 U1.AF2(OSC_OUT)
I2C1.SCL: R224.1 U1.P1(PG13) ; port I2C1.SCL
I2C1.SDA: R228.1 U1.M6(PI1) ; port I2C1.SDA
I2C2.SCL: R32.1 U1.AC15(PF2) ; port GPIO.I2C2.SCL, port PERIPH_I2C.I2C2.SCL
I2C2.SDA: R31.1 U1.AA15(PF0) ; port GPIO.I2C2.SDA, port PERIPH_I2C.I2C2.SDA
I2C7.SCL: R261.1 U1.E15(PD15) ; port I2C7.SCL
I2C7.SDA: R260.1 U1.E19(PD14) ; port I2C7.SDA
I2C8.SCL: R245.1 U1.V3(PZ4) ; port GPIO.I2C8.SCL  [project net EXP_GPIO3]
I2C8.SDA: R246.1 U1.Y6(PZ3) ; port GPIO.I2C8.SDA  [project net EXP_GPIO2]
JTCK_SWCLK: TP43.1 U1.AA5(JTCK_SWCLK) ; port STLINK_SWCLK
JTDI: TP41.1 U1.AE3(JTDI) ; port STLINK_JTDI
JTDO_SWDO: TP13.1 U1.AC2(JTDO_SWDO) ; port STLINK_SWO
JTMS_SWDIO: TP40.1 U1.AE2(JTMS_SWDIO) ; port STLINK_SWDIO
LED1: U1.AB16(PH4) ; port LED.LED1
LED2: U1.AG18(PH5) ; port LED.LED2
LED3: U1.AF19(PH6) ; port LED.LED3
LED4: U1.AE16(PH7) ; port LED.LED4
LPO_32: U1.U5(PI8) ; port WLBT_CTRL.LPO_32
MCO1: TP11.1 U1.AE4(PF11) ; port GPIO.MCO1  [project net EXP_GPIO4]
MDF.CCK: U1.AE18(PA7) ; port AUDIO.MDF.CCK
MDF.SDI6: U1.AF18(PA6) ; port AUDIO.MDF.SDI6
MP257_WAKEUP: U1.AF5(PA0) ; port MP257_WAKEUP
NJTRST: TP42.1 U1.AF3(NJTRST)
NRST: C33.2 U1.AE1(NRST) ; port NRST
NRSTC1MS: R27.1 R272.1 U1.W3(NRSTC1MS) ; port NRSTC1MS
OSC32_IN: C86.1 U1.AA2(OSC32_IN) X1.2(X2)
OSC32_OUT: R64.1 U1.AA1(OSC32_OUT)
PMIC_WAKEUPn: U1.W7(PC13) ; port PMIC_WAKEUPn
PWR_CPU_ON: R272.2 U1.AB4(PWR_CPUON) ; port PWR_CPU_ON
PWR_ON: U1.AD3(PWR_ON) ; port PWR_ON
SD.SDMMC1_CK: U1.C21(PE3) ; port SD.SDMMC1_CK
SD.SDMMC1_CMD: U1.C20(PE2) ; port SD.SDMMC1_CMD
SD.SDMMC1_D0: U1.B21(PE4)
SD.SDMMC1_D1: U1.C22(PE5)
SD.SDMMC1_D2: U1.B19(PE0)
SD.SDMMC1_D3: U1.C19(PE1)
SD.uSD_DETECT: U1.G13(PD3) ; port SD.uSD_DETECT
TCPP_EN: U1.AD18(PA3) ; port TCPP_EN
TCPP_INTN: U1.AD4(PG1) ; port TCPP_INTN
UART5_RX: R125.1 U1.M4(PG10) ; port UART5_RX
UART5_TX: U1.M3(PG9) ; port UART5_TX
USART1_CTS: U1.N7(PI3) ; port BT_UART.USART1_CTS
USART1_RTS: U1.N5(PI2) ; port BT_UART.USART1_RTS
USART1_RX: U1.K6(PG15) ; port BT_UART.USART1_RX
USART1_TX: U1.N1(PG14) ; port BT_UART.USART1_TX
USART2_RX: R107.1 U1.AA17(PA8) ; port USART2_RX
USART2_TX: U1.AG17(PA4) ; port USART2_TX
USBSW_OE: U1.AC17(PH2) ; port USBSW_OE
USBSW_S: U1.AE19(PH3) ; port USBSW_S
VBUS_DIV: TP35.1 U1.AE5(PF10) ; port VBUS_DIV
VCONN_CC1_EN: U1.AA11(PF5) ; port VCONN_CC1_EN
VCONN_CC2_EN: U1.AA9(PC3) ; port VCONN_CC2_EN
WL.SDMMC3_CK: U1.A26(PB13) ; port WL_SDIO.SDMMC3.CK
WL.SDMMC3_CMD: U1.B26(PD12) ; port WL_SDIO.SDMMC3.CMD
WL.SDMMC3_D0: U1.C27(PB14)
WL.SDMMC3_D1: U1.D25(PD13)
WL.SDMMC3_D2: U1.C26(PB12)
WL.SDMMC3_D3: U1.B27(PI11)
WL_HOST_WAKE: U1.N2(PG11) ; port WLBT_CTRL.WL_HOST_WAKE
WL_REG_ON: U1.L5(PG8) ; port WLBT_CTRL.WL_REG_ON
NetC81_1: C81.1 R64.2 X1.1(X1)
NetC92_1: C92.1 R75.1 X2.3
NetTP12_1: TP12.1 U1.AF1(PWR_LP)

Not connected (* = marked no-connect by the designer): U1 A15(PD11)* A18(PD6)* AA7(PG3)* AB10(PC6)* AC7(PF6)* AE7(PC12)* AE8(PF9)* AE9(PC9)* AE10(PF8)* AF7(PG0)* AG9(PC8)* B18(PD5)* C15(PD9)* C16(PD8)* C17(PD10)* C18(PD4)* D16(PI10)* D20(PD7)* N3(PG12)* U1(PI9)*

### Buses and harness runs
bus BOOT[0..3] = port BOOT[0..3]
bus eMMC.SDMMC2_D[0..7]
bus ETH1.RXD[0..3]
bus ETH1.TXD[0..3]
bus SD.SDMMC1_D[0..3]
bus WL.SDMMC3_D[0..3]

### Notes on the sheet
- uSD
- eMMC
- PHY_INTN
- TX_EN
- (near R205) RX_DV
- PMIC
- GPIO EXPANSION
- (near R205) ETHERNET
- I2C-I3C
- I3C4_SDA
- I3C4_SCL
- AUDIO
- PERIPH
- (near R75) BOOTFAILN
- LED-BUTTON
- MCO2
- MCO1
- ADC3P2
- VIDEO
- POWER - PMIC
- CAMERA
- USB
- (near R107) BOOT_VCPA35
- UART - DEBUG
- VCPM33
- BOOT MODE
- STLINK
- WLAN - BLE

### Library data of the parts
C33 = MCD-00011: Capacitor, MLCC, 10nF, 16V, X7R, 10%, 0402, T=0.5mm; Manufacturer_Part_Number: CC0402KRX7R7BB103; Manufacturer: YAGEO; Provided_By: SUBCO; Initial_Board_Reference: MB1274
C81 C86 = MCD-01775: Capacitor, MLCC, 3.3pF, 50V, NPO, +/-0.1pF, 0402, T=0.5mm; Part_Preference: Recommended; Manufacturer: YAGEO; Manufacturer_Part_Number: CC0402BRNPO9BN3R3; Component_Country_Of_Origin: China; ShowFields: YES; ID: 3875
C90 C92 = MCD-00674: Capacitor, MLCC, 6.8pF, 50V, NPO, +-0.25pF, 0402, T=0.5mm; Manufacturer_Part_Number: CC0402CRNPO9BN6R8; Manufacturer: YAGEO; Part_Preference: Recommended; Provided_By: SUBCO; Initial_Board_Reference: MB1319; Component_Country_Of_Origin: China; ID: 3068; ShowFields: YES
R27 R107 R125 R272 = MCD-00053: Resistor,10K,0402,1%,1/16W; BMS_Part_Number: 9131590; Part_Preference: Recommended; Manufacturer: YAGEO; Manufacturer_Part_Number: RC0402FR-0710KL; Component_Country_Of_Origin: China; ID: 2539; ShowFields: YES
R31 R32 R224 R228 R245 R246 R260 R261 = MCD-00068: Resistor,1K5,0402,1%,1/16W; Part_Preference: Recommended; Manufacturer: YAGEO; Manufacturer_Part_Number: RC0402FR-071K5L; Component_Country_Of_Origin: China; ID: 2524; ShowFields: YES
R64 R75 = MCD-00052: Resistor,0R,0402,5%,1/16W; Manufacturer_Part_Number: RC0402JR-070RL; Manufacturer: YAGEO; Part_Preference: Recommended; Provided_By: SUBCO; Initial_Board_Reference: mb1274; Order_Code_RS: 618-5804; Component_Country_Of_Origin: China; ID: 2540; ShowFields: YES
R205 = MCD-00053: as R33 on sheet Peripherals
TP11-TP13 TP30 TP35 TP40-TP43 = MCD-00074: as TP2 on sheet Peripherals
U1 = MCD-03375: MPU , 2xCortex-A35@1.5GHz, Cortex-M33@400MHz, TFBGA 14x14, pitch 0.5, 648KB SRAM, With Crypto; Part_Type: IC; Part_Preference: Recommended; Manufacturer: STMICROELECTRONICS; Component_Country_Of_Origin: Unknown; ShowFields: YES; ID: 5491
X1 = MCD-01479: Crystal, 32.768kHz, 6pF, +/-20ppm, 80K, 2.05x1.2mm; BMS_Part_Number: 9157049; Part_Type: Crystal_Osc; Part_Preference: Recommended; Manufacturer: NDK; Manufacturer_Part_Number: NX2012SA-32.768KHZ-EXS00A-MU00527; Component_Country_Of_Origin: Unknown; ShowFields: YES; ID: 3579
X2 = MCD-02344: Crystal, 40MHz, 6pF, +/-20ppm, 80R, 1.6x1.2mm; Part_Type: Crystal_Osc; Part_Preference: Recommended; Manufacturer: NDK; Manufacturer_Part_Number: NX1612SA-40MHZ-EXS00A-CS13836; Component_Country_Of_Origin: Unknown; ShowFields: YES; ID: 4450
